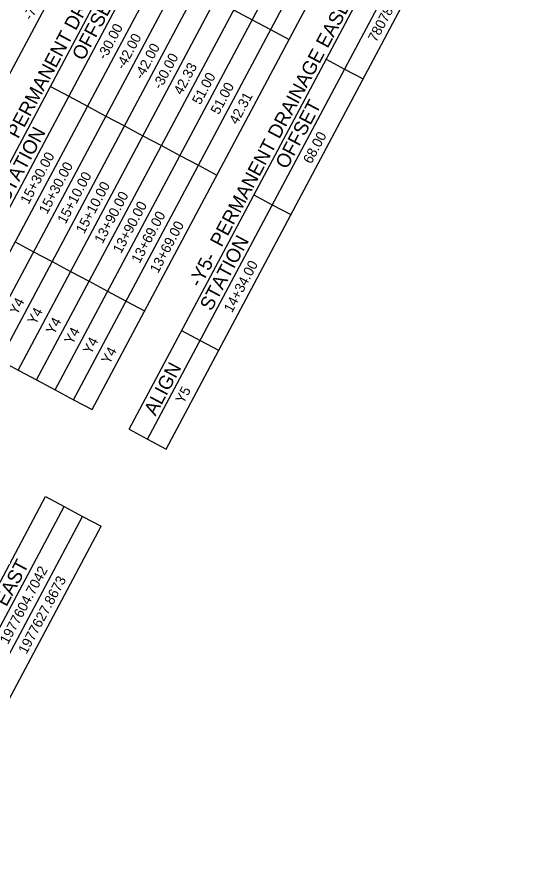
# Model space of a CAD drawing. Extents: x 1979034 to 1987549, y 771535 to 781988.
# Drawn here: x 1984093 to 1985259, y 775446 to 777368 of the extents above; entities that cross this region are included whole.
import ezdxf

# ---------------------------------------------------------------- set-up
doc = ezdxf.new("R2010")
doc.units = 0
for name, color, linetype in [('CTL Sheet Notes CELL', 7, 'Continuous'), ('CTL Sheet Table Cell', 7, 'Continuous'), ('CTL Sheet Text', 7, 'Continuous')]:
    doc.layers.add(name, color=color, linetype=linetype)

msp = doc.modelspace()

# ---------------------------------------------------------------- linework, layer by layer
at = {"layer": 'CTL Sheet Table Cell'}
for p, q in [((1983803.7, 776727.4), (1984633.3, 778284.2)), ((1983887.1, 776683), (1984716.7, 778239.7)), ((1983928.8, 776660.8), (1984758.4, 778217.5)), ((1983970.5, 776638.5), (1984800.1, 778195.3)), ((1984012.2, 776616.3), (1984841.7, 778173.1)), ((1984053.9, 776594.1), (1984883.4, 778150.9)), ((1984095.6, 776571.9), (1984925.1, 778128.6)), ((1984137.3, 776549.7), (1984966.8, 778106.4)), ((1984179, 776527.4), (1985008.5, 778084.2)), ((1984220.7, 776505.2), (1985050.2, 778062)), ((1984262.4, 776483), (1985091.9, 778039.8)), ((1984345.8, 776438.6), (1985175.3, 777995.3)), ((1984387.5, 776416.3), (1985217, 777973.1)), ((1984429.2, 776394.1), (1985258.7, 777950.9)), ((1984581.7, 777383.6), (1984623.4, 777361.4)), ((1984623.4, 777361.4), (1984665.1, 777339.2)), ((1984665.1, 777339.2), (1984706.8, 777317)), ((1984790.2, 777272.5), (1984831.9, 777250.3)), ((1984831.9, 777250.3), (1984873.6, 777228.1)), ((1984168.5, 777211.2), (1984210.2, 777188.9)), ((1984210.2, 777188.9), (1984251.9, 777166.7)), ((1984251.9, 777166.7), (1984293.6, 777144.5)), ((1984293.6, 777144.5), (1984335.3, 777122.3)), ((1984335.3, 777122.3), (1984377, 777100.1)), ((1984377, 777100.1), (1984418.7, 777077.8)), ((1984418.7, 777077.8), (1984460.4, 777055.6)), ((1984460.4, 777055.6), (1984502.1, 777033.4)), ((1984502.1, 777033.4), (1984543.8, 777011.2)), ((1984627.2, 776966.7), (1984668.9, 776944.5)), ((1984668.9, 776944.5), (1984710.6, 776922.3)), ((1984089, 776860.9), (1984130.7, 776838.7)), ((1984130.7, 776838.7), (1984172.4, 776816.5)), ((1984172.4, 776816.5), (1984214.1, 776794.3)), ((1984214.1, 776794.3), (1984255.8, 776772.1)), ((1984255.8, 776772.1), (1984297.5, 776749.8)), ((1984297.5, 776749.8), (1984339.2, 776727.6)), ((1984339.2, 776727.6), (1984380.9, 776705.4)), ((1984464.3, 776660.9), (1984506, 776638.7)), ((1984506, 776638.7), (1984547.7, 776616.5)), ((1984053.9, 776594.1), (1984095.6, 776571.9)), ((1984095.6, 776571.9), (1984137.3, 776549.7)), ((1984137.3, 776549.7), (1984179, 776527.4)), ((1984179, 776527.4), (1984220.7, 776505.2)), ((1984220.7, 776505.2), (1984262.4, 776483)), ((1984345.8, 776438.6), (1984387.5, 776416.3)), ((1984387.5, 776416.3), (1984429.2, 776394.1)), ((1983328.2, 774730.1), (1984157.8, 776286.8)), ((1984157.8, 776286.8), (1984199.5, 776264.6)), ((1983369.9, 774707.9), (1984199.5, 776264.6)), ((1984199.5, 776264.6), (1984241.2, 776242.4)), ((1983411.6, 774685.6), (1984241.2, 776242.4)), ((1984241.2, 776242.4), (1984282.9, 776220.2)), ((1983453.3, 774663.4), (1984282.9, 776220.2))]:
    msp.add_line(p, q, dxfattribs=at)

# ---------------------------------------------------------------- texts
at = {"layer": 'CTL Sheet Notes CELL'}
for s, p in [('-Y4-  PERMANENT DRAINAGE EASEMENTS', (1984047.5, 777000.8)), ('-Y5-  PERMANENT DRAINAGE EASEMENTS', (1984506.2, 776756.4)), ('OFFSET', (1984243.1, 777267.4)), ('OFFSET', (1984701.8, 777023)), ('STATION', (1984072.8, 776947.8)), ('STATION', (1984531.5, 776703.4)), ('ALIGN', (1984405.5, 776466.9)), ('EAST', (1984069.3, 776037.1))]:
    msp.add_text(s, height=31.5, rotation=61.9471, dxfattribs=at).set_placement(p)
at = {"layer": 'CTL Sheet Text'}
for s, p in [('780783.5087', (1984903, 777309.5)), ('-73.88', (1984125.9, 777358.5)), ('-30.00', (1984292.7, 777269.6)), ('-42.00', (1984334.4, 777247.4)), ('-42.00', (1984376.1, 777225.2)), ('-30.00', (1984417.8, 777203)), ('42.33', (1984464.8, 777190.6)), ('51.00', (1984506.5, 777168.4)), ('51.00', (1984548.2, 777146.1)), ('42.31', (1984589.9, 777123.9)), ('68.00', (1984756.7, 777035)), ('15+30.00', (1984119.3, 776944.1)), ('15+30.00', (1984161, 776921.9)), ('15+10.00', (1984202.7, 776899.7)), ('15+10.00', (1984244.4, 776877.5)), ('13+90.00', (1984286.1, 776855.3)), ('13+90.00', (1984327.8, 776833)), ('13+69.00', (1984369.5, 776810.8)), ('13+69.00', (1984411.2, 776788.6)), ('14+34.00', (1984578, 776699.7)), ('Y4', (1984093.4, 776694.7)), ('Y4', (1984135.1, 776672.5)), ('Y4', (1984176.8, 776650.3)), ('Y4', (1984218.5, 776628)), ('Y4', (1984260.2, 776605.8)), ('Y4', (1984301.9, 776583.6)), ('Y5', (1984468.7, 776494.7)), ('1977604.7042', (1984072.8, 775952.6)), ('1977627.8673', (1984114.5, 775930.4))]:
    msp.add_text(s, height=22.5, rotation=61.9471, dxfattribs=at).set_placement(p)

doc.saveas('drawing.dxf')
